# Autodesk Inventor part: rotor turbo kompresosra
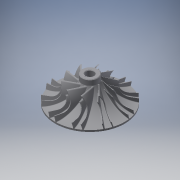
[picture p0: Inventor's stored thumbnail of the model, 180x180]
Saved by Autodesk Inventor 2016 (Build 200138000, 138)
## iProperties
Created: 2015-03
Part Number: rotor turbo kompresosra
Material: Generic
Document SubType Name: Modeling
Designer: Uglješa
Density: 1 g/cm^3
Appearance: Default
Mass: 181.59 g
Surface Area: 557.817 cm^2
Volume: 181.59 cm^3
Author: Uglješa
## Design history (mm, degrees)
sketch "Sketch1"
  geometry: L1 (0, 78.056)-(0, -95.023); L2 (0, 50)-(15, 50); L3 (15, 50)-(15, 40); L4 (69, 3)-(69, 0); L5 (0, 50)-(0, -5); L6 (0, -5)-(15, -5); L7 (69, 0)-(35, 0); A1 r 42.5 centre (35, -42.5) between (35, 0) and (15, -5); A2 r 57.905 centre (69, 60.905) between (15, 40) and (69, 3); 1 further point
  constraints: 14 end point, 5 point on line, 4 point on circle, 2 centre point, 2 perpendicular, 1 parallel, 1 tangent, 1 vertical
  dimensions: "d0" = 10 distance of L2.end L3.end; "d3" = 30 diameter of L3 L1; "d4" = 50 distance from line of point (0, 0) L2; "d6" = 3 distance of L4.start L4.end; "d7" = 138 diameter of L4 L1; "d8" = 55 distance between parallel lines of L6 L2; "d9" = 70 diameter of L7.end L1; "d10" = 30 diameter of L6.end L1
revolve "Revolution1" sketch "Sketch1" stored, may be unused: angle "d11" = 90 deg
workplane "Work Plane2"
  workplane "Work Plane1"
workplane "Work Plane3"
sketch "Sketch3"
  geometry: L1 (69, 0)-(65.623, 21.322); L2 (65.623, 21.322)-(55.822, 40.557); L3 (55.822, 40.557)-(40.557, 55.822); L4 (40.557, 55.822)-(21.322, 65.623); L5 (21.322, 65.623)-(0, 69); L6 (-21.322, 65.623)-(-40.557, 55.822); L7 (-40.557, 55.822)-(-55.822, 40.557); L8 (-55.822, 40.557)-(-65.623, 21.322); L9 (-65.623, 21.322)-(-69, 0); L10 (-69, 0)-(-65.623, -21.322); L11 (-65.623, -21.322)-(-55.822, -40.557); L12 (-55.822, -40.557)-(-40.557, -55.822); L13 (-40.557, -55.822)-(-21.322, -65.623); L14 (-21.322, -65.623)-(0, -69); L15 (0, -69)-(21.322, -65.623); L16 (21.322, -65.623)-(40.557, -55.822); L17 (40.557, -55.822)-(55.822, -40.557); L18 (55.822, -40.557)-(65.623, -21.322); L19 (65.623, -21.322)-(69, 0); L20 (-21.322, 65.623)-(0, 69); 2 further points
  constraints: 40 end point, 11 perpendicular, 2 parallel, 1 vertical alignment, 22 other
  dimensions: "d23" = 360 deg dimension on point (0, 0) L5.end (derived)
sketch "Sketch6"
  geometry: L1 (0, 0)-(0, 90.593) reference; L2 (-15, 0)-(32.767, 60.723); L3 (0, 0)-(-134.085, 0); C1 r 37.5 at (0, 0); A1 r 15 centre (0, 0) between (5.293, 14.035) and (-15, 0) reference; 1 further point
  constraints: 6 end point, 2 point on circle, 2 vertical, 1 centre point, 1 coincident, 1 perpendicular, 2 other
  dimensions: "d31" = 75 diameter of C1; "d208" = 38.19 deg angle of L2 L1; "d216" = 0 distance from line of L2.start L3
workplane "Work Plane7"
sketch "Sketch12"
  geometry: L1 (-6.768, 23)-(0, 3); A1 r 25 centre (-30.449, 14.986) between (-6.768, 23) and (-26.355, 39.649); 1 further point
  constraints: 2 end point, 2 point on circle, 1 centre point, 1 tangent
  dimensions: "d264" = 25 radius of A1; "d266" = 20 vertical distance of L1.start L1.end
sketch "Sketch13"
  geometry: L1 (15, 0)-(15, 40); L2 (-69, 0)-(69, 0) reference; 1 further point
  constraints: 2 end point, 1 point on line, 1 vertical
  dimensions: "d93" = 40 distance of L1.start L1.end
feature "LoftSrf21" sketch "Sketch12", "Sketch13" dims "d108" = 0, "d109" = 90 deg, "d110" = 0, "d111" = 90 deg
pattern_circular "Circular Pattern3" dims angle "d113" = 360 deg
sketch "Sketch14"
  geometry: L1 (-0.509, -25.606)-(-0.509, -41.551) reference; L2 (-0.509, 76.402)-(91.556, 76.402); L3 (91.556, 76.402)-(91.556, -5); L4 (91.556, -5)-(66.991, -5); L5 (66.991, -5)-(66.991, 20); L6 (-15, -5)-(15, -5) reference; L7 (-0.509, 76.402)-(0, 58.172); L8 (0, 58.172)-(15, 58.591); L9 (15, 58.591)-(15.519, 40); L10 (15.519, 40)-(38.706, 40); A1 r 30 centre (66.991, 50) between (38.706, 40) and (66.991, 20); 2 further points
  constraints: 18 end point, 4 parallel, 4 point on line, 3 perpendicular, 2 point on circle, 2 vertical, 1 centre point, 1 midpoint
  dimensions: "d162" = 135 diameter of L5 L1; "d164" = 30 radius of A1; "d165" = 25 distance of L4.end L5.end
revolve "Revolution5" sketch "Sketch14" stored, may be unused: angle "d166" = 90 deg
sketch "Sketch15"
  geometry: C1 r 15 at (0, 0) reference; C2 r 7.5 at (0, 0)
  constraints: 1 centre point, 1 coincident
  dimensions: "d167" = 15 diameter of C2
extrude "Extrusion5" cut sketch "Sketch15" stored distance "d169" = 10; taper "d170" = 0 deg
pattern_circular "Circular Pattern4" dims angle "d181" = 360 deg
thicken "Thicken23" dims "d183" = 1.25, "d184" = 1.25
thicken "Thicken24" dims "d185" = 1.25, "d186" = 1.25
thicken "Thicken25" dims "d187" = 1.25, "d188" = 1.25
thicken "Thicken26" dims "d189" = 1.25, "d190" = 1.25
thicken "Thicken27" dims "d191" = 1.25, "d192" = 1.25
thicken "Thicken28" dims "d193" = 1.25, "d194" = 1.25
thicken "Thicken29" dims "d195" = 1.25, "d196" = 1.25
thicken "Thicken30" dims "d197" = 1.25, "d198" = 1.25
thicken "Thicken31" dims "d199" = 1.25, "d200" = 1.25
thicken "Thicken32" dims "d201" = 1.25, "d202" = 1.25
sketch "Sketch18"
  geometry: L1 (-15, 3)-(-21.167, 19.943); L2 (-109.617, 30)-(174.702, 30) reference; L3 (0, -26.248)-(0, -9.678) reference; A1 r 18 centre (-38.081, 13.787) between (-21.167, 19.943) and (-30.262, 30); 1 further point
  constraints: 4 end point, 2 point on circle, 1 centre point, 1 perpendicular, 1 point on line, 1 tangent, 1 vertical
  dimensions: "d221" = 18 radius of A1; "d272" = 16.94343 vertical distance of L1.start L1.end; "d273" = 15 horizontal distance of point (0, 0) L1.start; "d274" = 3 vertical distance of point (0, 0) L1.start; "d275" = 20 deg angle of L3 L1
sketch "Sketch19"
  geometry: L1 (15, 30.003)-(15, 2.916); L2 (0, 57.914)-(0, 52.147) reference; 1 further point
  constraints: 4 end point, 2 vertical, 1 parallel
  dimensions: "d224" = 30 diameter of L1 L2
feature "LoftSrf60" sketch "Sketch18", "Sketch19" dims "d226" = 0, "d227" = 90 deg, "d228" = 0, "d229" = 90 deg
pattern_circular "Circular Pattern5" dims angle "d231" = 360 deg
thicken "Thicken33" dims "d233" = 1.25, "d234" = 1.25
thicken "Thicken34" dims "d235" = 1.25, "d236" = 1.25
thicken "Thicken35" dims "d237" = 1.25, "d238" = 1.25
thicken "Thicken36" dims "d239" = 1.25, "d240" = 1.25
thicken "Thicken37" dims "d241" = 1.25, "d242" = 1.25
thicken "Thicken38" dims "d243" = 1.25, "d244" = 1.25
thicken "Thicken39" dims "d245" = 1.25, "d246" = 1.25
thicken "Thicken40" dims "d247" = 1.25, "d248" = 1.25
thicken "Thicken41" dims "d249" = 1.25, "d250" = 1.25
thicken "Thicken42" dims "d251" = 1.25, "d252" = 1.25
sketch "Sketch16"
  geometry: L1 (0, 0)-(0, 0) reference; L2 (41.735, 62.973)-(111.445, 62.973); L3 (111.445, 62.973)-(124.053, 27.311); L4 (66, 12)-(66, -14.252); L5 (66, -14.252)-(124.053, -14.252); L6 (124.053, -14.252)-(124.053, 27.311); L7 (39, 27)-(39, 52.349); L8 (39, 52.349)-(39, 62.973); L9 (39, 62.973)-(41.735, 62.973); L10 (54, 12)-(66, 12); L11 (0, 120.354)-(0, -39.329) reference; A1 r 15 centre (54, 27) between (39, 27) and (54, 12); 1 further point
  constraints: 20 end point, 3 point on circle, 2 parallel, 2 perpendicular, 2 tangent, 2 vertical, 1 centre point, 1 horizontal
  dimensions: "d258" = 15 radius of A1; "d260" = 12 distance from line of L1 L4.start; "d280" = 132 diameter of L4 L11
fillet "Fillet13" dims "d254" = 1
fillet "Fillet15" dims "d256" = 2.5
chamfer "Chamfer1" distance "d261" = 1; stored, may be unused: second distance "d262" = 2, angle "d263" = 45 deg
fillet "Fillet16" dims "d270" = 2.5
revolve "Revolution7" stored, may be unused: angle "d278" = 90 deg
sketch "Sketch20"
  geometry: L1 (0, 0)-(0, -2.719); L2 (0.5, -10)-(-0.5, -10); L3 (-0.5, -10)-(-0.5, -4.611); L4 (-0.5, -4.611)-(0.5, -4.611); L5 (0.5, -4.611)-(0.5, -10)
  constraints: 10 end point, 2 parallel, 1 horizontal, 1 perpendicular, 1 vertical
  dimensions: "d281" = 10 distance from line of L2 L1.start; "d282" = 1 distance between parallel lines of L5 L3; "d283" = 1 diameter of L5 L1
extrude "Extrusion6" cut sketch "Sketch20" distance "d284" = 0.5; taper "d285" = 0 deg
body "Solid1"
body "Srf23"
body "Srf24"
body "Srf25"
body "Srf26"
body "Srf27"
body "Srf28"
body "Srf29"
body "Srf30"
body "Srf31"
body "Srf32"
body "Srf43"
body "Srf44"
body "Srf45"
body "Srf46"
body "Srf47"
body "Srf48"
body "Srf49"
body "Srf50"
body "Srf51"
body "Srf62"
body "Srf63"
body "Srf64"
body "Srf65"
body "Srf66"
body "Srf67"
body "Srf68"
body "Srf69"
body "Srf70"
body "Srf71"
feature "LoftSrf22"
feature "LoftSrf23"
feature "LoftSrf24"
feature "LoftSrf25"
feature "LoftSrf26"
feature "LoftSrf27"
feature "LoftSrf28"
feature "LoftSrf29"
feature "LoftSrf30"
feature "LoftSrf41"
feature "LoftSrf42"
feature "LoftSrf43"
feature "LoftSrf44"
feature "LoftSrf45"
feature "LoftSrf46"
feature "LoftSrf47"
feature "LoftSrf48"
feature "LoftSrf49"
feature "LoftSrf61"
feature "LoftSrf62"
feature "LoftSrf63"
feature "LoftSrf64"
feature "LoftSrf65"
feature "LoftSrf66"
feature "LoftSrf67"
feature "LoftSrf68"
feature "LoftSrf69"
other parameters: "d18" = -3, "d81" = 75
